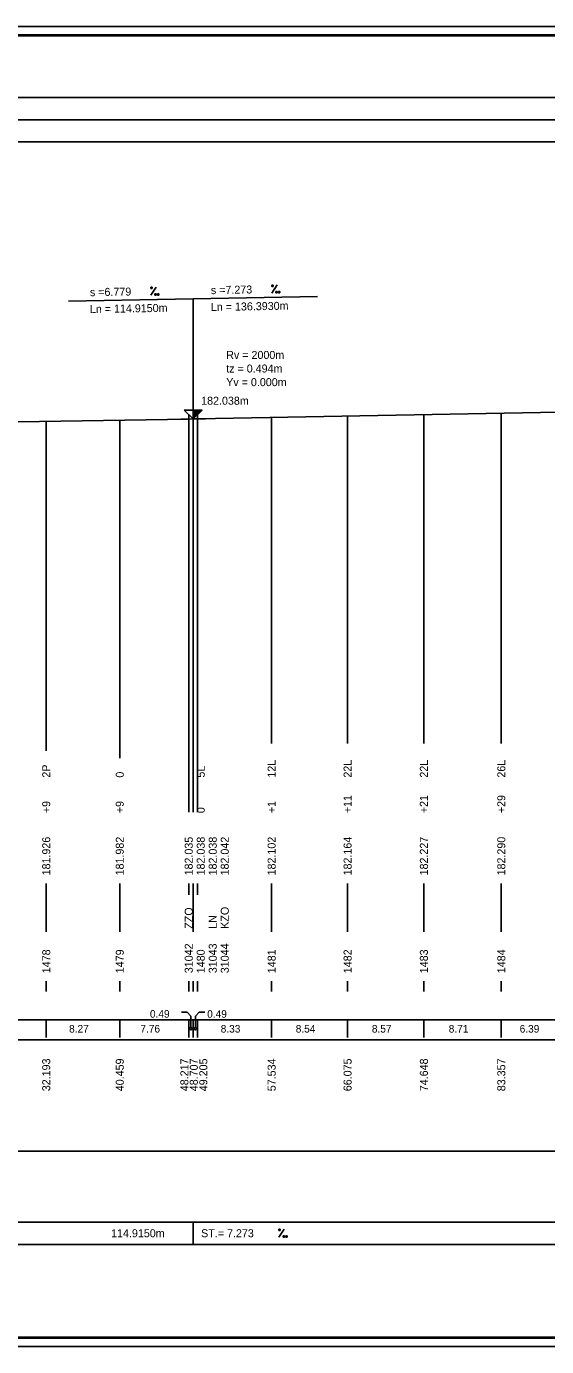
# Model space of a CAD drawing. Extents: x 0 to 10087, y -805 to 297.
# Drawn here: x 3839.9 to 3956.9, y 0 to 297 of the extents above; entities that cross this region are included whole.
import ezdxf

# ---------------------------------------------------------------- set-up
doc = ezdxf.new("R2010")
doc.units = 0
for name, color, linetype in [('CARKY_HODNOT', 7, 'Continuous'), ('KRIV1_CARA', 7, 'Continuous'), ('NIVELETA_CARA', 7, 'Continuous'), ('NIVELETA_TEXT', 7, 'Continuous'), ('RAM', 7, 'Continuous'), ('STAN_CARA', 7, 'Continuous'), ('STAN_PAS', 7, 'Continuous'), ('STAN_TEXT', 7, 'Continuous'), ('TEXT', 7, 'Continuous'), ('TXT_C_BODU', 7, 'Continuous')]:
    doc.layers.add(name, color=color, linetype=linetype)

msp = doc.modelspace()

# ---------------------------------------------------------------- linework, layer by layer
at = {"layer": 'CARKY_HODNOT'}
for p, q in [((3844.39, 138.35), (3844.39, 208.13)), ((3860.92, 138.35), (3860.92, 208.41)), ((3876.43, 138.35), (3876.43, 208.67)), ((3877.41, 138.35), (3877.41, 208.69)), ((3877.42, 138.35), (3877.42, 208.69)), ((3878.41, 138.35), (3878.41, 208.71)), ((3895.07, 138.35), (3895.07, 209.01)), ((3912.15, 138.35), (3912.15, 209.32)), ((3929.3, 138.35), (3929.3, 209.63)), ((3946.71, 138.35), (3946.71, 209.95)), ((3844.39, 134), (3844.39, 138.35)), ((3860.92, 132.35), (3860.92, 138.35)), ((3876.43, 126.2), (3876.43, 138.35)), ((3877.41, 134), (3877.41, 138.35)), ((3877.42, 126.2), (3877.42, 138.35)), ((3878.41, 126.2), (3878.41, 138.35)), ((3895.07, 135.65), (3895.07, 138.35)), ((3912.15, 135.65), (3912.15, 138.35)), ((3929.3, 135.65), (3929.3, 138.35)), ((3946.71, 135.65), (3946.71, 138.35)), ((3876.43, 120.25), (3876.43, 126.2)), ((3877.41, 124.35), (3877.41, 126.2)), ((3877.42, 120.25), (3877.42, 126.2)), ((3878.41, 120.25), (3878.41, 126.2)), ((3844.39, 93.3), (3844.39, 104.2)), ((3860.92, 93.3), (3860.92, 104.2)), ((3876.43, 101.65), (3876.43, 104.2)), ((3877.41, 93.3), (3877.41, 104.2)), ((3877.42, 100), (3877.42, 104.2)), ((3878.41, 101.65), (3878.41, 104.2)), ((3895.07, 93.3), (3895.07, 104.2)), ((3912.15, 93.3), (3912.15, 104.2)), ((3929.3, 93.3), (3929.3, 104.2)), ((3946.71, 93.3), (3946.71, 104.2)), ((3844.39, 79.9), (3844.39, 82.2)), ((3860.92, 79.9), (3860.92, 82.2)), ((3876.43, 79.9), (3876.43, 82.2)), ((3877.41, 79.9), (3877.41, 82.2)), ((3877.42, 79.9), (3877.42, 82.2)), ((3878.41, 79.9), (3878.41, 82.2)), ((3895.07, 79.9), (3895.07, 82.2)), ((3912.15, 79.9), (3912.15, 82.2)), ((3929.3, 79.9), (3929.3, 82.2)), ((3946.71, 79.9), (3946.71, 82.2))]:
    msp.add_line(p, q, dxfattribs=at)
at = {"layer": 'KRIV1_CARA'}
msp.add_line((3580.41, 44), (4035.16, 44), dxfattribs=at)
at = {"layer": 'NIVELETA_CARA'}
for p, q in [((300, 281), (8321.33, 281)), ((300, 276), (8321.33, 276)), ((300, 271), (8321.33, 271)), ((3877.42, 235.69), (3849.42, 235.22)), ((3877.42, 235.69), (3905.42, 236.2)), ((3877.42, 208.69), (3877.42, 235.69)), ((3878.41, 208.71), (4145.86, 213.57)), ((3657.48, 204.96), (3876.43, 208.67)), ((3876.43, 208.67), (3874.62, 208.64)), ((3877.42, 208.69), (3875.42, 210.69)), ((3875.42, 210.69), (3879.42, 210.69)), ((3876.43, 208.67), (3876.43, 209.67)), ((3876.43, 208.67), (3877.42, 208.69)), ((3877.42, 208.69), (3877.42, 210.69)), ((3879.42, 210.69), (3877.42, 208.69)), ((3877.42, 208.69), (3878.41, 208.71)), ((3877.49, 208.76), (3877.49, 210.69)), ((3877.56, 208.82), (3877.56, 210.69)), ((3877.62, 208.89), (3877.62, 210.69)), ((3877.69, 208.96), (3877.69, 210.69)), ((3877.76, 209.02), (3877.76, 210.69)), ((3877.82, 209.09), (3877.82, 210.69)), ((3877.89, 209.16), (3877.89, 210.69)), ((3877.96, 209.22), (3877.96, 210.69)), ((3878.02, 209.29), (3878.02, 210.69)), ((3878.09, 209.36), (3878.09, 210.69)), ((3878.16, 209.42), (3878.16, 210.69)), ((3878.22, 209.49), (3878.22, 210.69)), ((3878.29, 209.56), (3878.29, 210.69)), ((3878.36, 209.62), (3878.36, 210.69)), ((3878.41, 208.71), (3878.41, 209.71)), ((3880.22, 208.74), (3878.41, 208.71)), ((3878.42, 209.69), (3878.42, 210.69)), ((3878.49, 209.76), (3878.49, 210.69)), ((3878.56, 209.82), (3878.56, 210.69)), ((3878.62, 209.89), (3878.62, 210.69)), ((3878.69, 209.96), (3878.69, 210.69)), ((3878.76, 210.02), (3878.76, 210.69)), ((3878.82, 210.09), (3878.82, 210.69)), ((3878.89, 210.16), (3878.89, 210.69)), ((3878.96, 210.22), (3878.96, 210.69)), ((3879.02, 210.29), (3879.02, 210.69)), ((3879.09, 210.36), (3879.09, 210.69)), ((3879.16, 210.42), (3879.16, 210.69)), ((3879.22, 210.49), (3879.22, 210.69)), ((3879.29, 210.56), (3879.29, 210.69)), ((3879.36, 210.62), (3879.36, 210.69)), ((500, 28), (8321.33, 28)), ((3877.42, 23), (3877.42, 28)), ((500, 23), (8321.33, 23))]:
    msp.add_line(p, q, dxfattribs=at)
at = {"layer": 'NIVELETA_TEXT'}
for p, q in [((3867.89, 238.33), (3867.9, 238.03)), ((3867.9, 238.33), (3867.89, 238.32)), ((3868.19, 238.33), (3867.9, 238.33)), ((3867.9, 238.03), (3868.19, 238.03)), ((3867.92, 236.53), (3869.08, 238.35)), ((3868.19, 238.03), (3868.19, 238.33)), ((3895.09, 238.81), (3895.09, 238.51)), ((3895.1, 238.81), (3895.09, 238.8)), ((3895.09, 238.51), (3895.39, 238.52)), ((3895.39, 238.81), (3895.1, 238.81)), ((3895.12, 237.02), (3896.28, 238.83)), ((3895.39, 238.52), (3895.39, 238.81)), ((3869.12, 236.85), (3868.83, 236.84)), ((3868.83, 236.84), (3868.83, 236.55)), ((3868.83, 236.84), (3868.83, 236.84)), ((3868.83, 236.55), (3869.13, 236.55)), ((3869.13, 236.55), (3869.12, 236.85)), ((3869.44, 236.85), (3869.44, 236.56)), ((3869.45, 236.85), (3869.44, 236.85)), ((3869.44, 236.56), (3869.74, 236.56)), ((3869.74, 236.86), (3869.45, 236.85)), ((3869.74, 236.56), (3869.74, 236.86)), ((3896.03, 237.33), (3896.03, 237.03)), ((3896.32, 237.33), (3896.03, 237.33)), ((3896.03, 237.33), (3896.03, 237.32)), ((3896.03, 237.03), (3896.33, 237.04)), ((3896.33, 237.04), (3896.32, 237.33)), ((3896.64, 237.34), (3896.64, 237.04)), ((3896.94, 237.34), (3896.64, 237.34)), ((3896.64, 237.34), (3896.64, 237.33)), ((3896.64, 237.04), (3896.94, 237.05)), ((3896.94, 237.05), (3896.94, 237.34)), ((3896.72, 24.6), (3897.91, 26.4)), ((3896.72, 26.4), (3896.72, 26.1)), ((3896.73, 26.4), (3896.72, 26.39)), ((3896.72, 26.1), (3897.02, 26.1)), ((3897.02, 26.4), (3896.73, 26.4)), ((3897.02, 26.1), (3897.02, 26.4)), ((3897.63, 24.9), (3897.63, 24.6)), ((3897.64, 24.9), (3897.63, 24.89)), ((3897.63, 24.6), (3897.93, 24.6)), ((3897.93, 24.9), (3897.64, 24.9)), ((3897.93, 24.6), (3897.93, 24.9)), ((3898.25, 24.9), (3898.25, 24.6)), ((3898.54, 24.9), (3898.25, 24.9)), ((3898.25, 24.9), (3898.25, 24.89)), ((3898.25, 24.6), (3898.54, 24.6)), ((3898.54, 24.6), (3898.54, 24.9))]:
    msp.add_line(p, q, dxfattribs=at)
at = {"layer": 'RAM'}
for p, q in [((8636.33, 297), (0, 297)), ((8634.33, 295.1), (2, 295.1)), ((8634.33, 295), (2, 295)), ((8634.33, 294.9), (2, 294.9)), ((0, 0), (8636.33, 0)), ((2, 2.1), (8634.33, 2.1)), ((2, 2), (8634.33, 2)), ((2, 1.9), (8634.33, 1.9))]:
    msp.add_line(p, q, dxfattribs=at)
at = {"layer": 'STAN_CARA'}
msp.add_line((3781, 69), (3979, 69), dxfattribs=at)
at = {"layer": 'STAN_PAS'}
for p, q in [((3876.07, 75.2), (3874.8, 75.2)), ((3876.92, 74.35), (3876.07, 75.2)), ((3876.92, 71.75), (3876.92, 74.35)), ((3877.92, 74.35), (3878.77, 75.2)), ((3877.92, 71.75), (3877.92, 74.35)), ((3878.77, 75.2), (3880.04, 75.2)), ((300, 73.5), (8321.33, 73.5)), ((3844.39, 69.5), (3844.39, 73.5)), ((3860.92, 69.5), (3860.92, 73.5)), ((3876.43, 69.5), (3876.43, 73.5)), ((3877.41, 69.5), (3877.41, 73.5)), ((3877.42, 69.5), (3877.42, 73.5)), ((3878.41, 69.5), (3878.41, 73.5)), ((3895.07, 69.5), (3895.07, 73.5)), ((3912.15, 69.5), (3912.15, 73.5)), ((3929.3, 69.5), (3929.3, 73.5)), ((3946.71, 69.5), (3946.71, 73.5))]:
    msp.add_line(p, q, dxfattribs=at)
for centre in [(3876.92, 71.5), (3877.92, 71.5)]:
    msp.add_circle(centre, 0.25, dxfattribs=at)

# ---------------------------------------------------------------- texts
at = {"layer": 'NIVELETA_TEXT'}
for s, rotation, p in [('s =6.779', 0.9709, (3854.22, 236.3)), ('s =7.273', 1.0417, (3881.42, 236.76)), ('Ln = 136.3930m', 1.0417, (3881.42, 232.96)), ('Ln = 114.9150m', 0.9709, (3854.22, 232.5))]:
    msp.add_text(s, height=1.8, rotation=rotation, dxfattribs=at).set_placement(p)
for s, p in [('Rv = 2000m', (3884.86, 222.19)), ('tz = 0.494m', (3884.86, 219.13)), ('Yv = 0.000m', (3884.86, 216.07)), ('182.038m', (3879.22, 211.89)), ('114.9150m', (3858.97, 24.6)), ('ST.= 7.273', (3879.22, 24.6))]:
    msp.add_text(s, height=1.8, dxfattribs=at).set_placement(p)
at = {"layer": 'STAN_TEXT'}
for s, p in [('0.49', (3867.71, 74)), ('0.49', (3880.58, 73.98)), ('8.27', (3849.53, 70.65)), ('7.76', (3865.56, 70.65)), ('8.33', (3883.62, 70.65)), ('8.54', (3900.49, 70.65)), ('8.57', (3917.61, 70.65)), ('8.71', (3934.89, 70.65)), ('6.39', (3950.84, 70.64))]:
    msp.add_text(s, height=1.7, dxfattribs=at).set_placement(p)
for s, p in [('32.193', (3845.29, 57.45)), ('40.459', (3861.82, 57.45)), ('48.217', (3876.35, 57.45)), ('48.707', (3878.47, 57.45)), ('49.205', (3880.61, 57.45)), ('57.534', (3895.97, 57.45)), ('66.075', (3913.05, 57.45)), ('74.648', (3930.2, 57.45)), ('83.357', (3947.61, 57.45))]:
    msp.add_text(s, height=1.8, rotation=90, dxfattribs=at).set_placement(p)
at = {"layer": 'TEXT'}
for s, p in [('2P', (3845.29, 128)), ('12L', (3895.97, 128)), ('22L', (3913.05, 128)), ('22L', (3930.2, 128)), ('26L', (3947.61, 128)), ('0', (3861.82, 128)), ('5L', (3880.03, 128)), ('+9', (3845.29, 120)), ('+9', (3861.82, 120)), ('+1', (3895.97, 120)), ('+11', (3913.05, 120)), ('+21', (3930.2, 120)), ('+29', (3947.61, 120)), ('0', (3880.03, 120)), ('181.926', (3845.29, 106)), ('181.982', (3861.82, 106)), ('182.035', (3877.33, 106)), ('182.038', (3880.03, 106)), ('182.038', (3882.73, 106)), ('182.042', (3885.43, 106)), ('182.102', (3895.97, 106)), ('182.164', (3913.05, 106)), ('182.227', (3930.2, 106)), ('182.290', (3947.61, 106)), ('ZZO', (3877.33, 94)), ('KZO', (3885.43, 94)), ('LN', (3882.73, 94))]:
    msp.add_text(s, height=1.8, rotation=90, dxfattribs=at).set_placement(p)
at = {"layer": 'TXT_C_BODU'}
for s, p in [('1478', (3845.29, 84)), ('1479', (3861.82, 84)), ('31042', (3877.33, 84)), ('1480', (3880.03, 84)), ('31043', (3882.73, 84)), ('31044', (3885.43, 84)), ('1481', (3895.97, 84)), ('1482', (3913.05, 84)), ('1483', (3930.2, 84)), ('1484', (3947.61, 84))]:
    msp.add_text(s, height=1.8, rotation=90, dxfattribs=at).set_placement(p)

doc.saveas('drawing.dxf')
